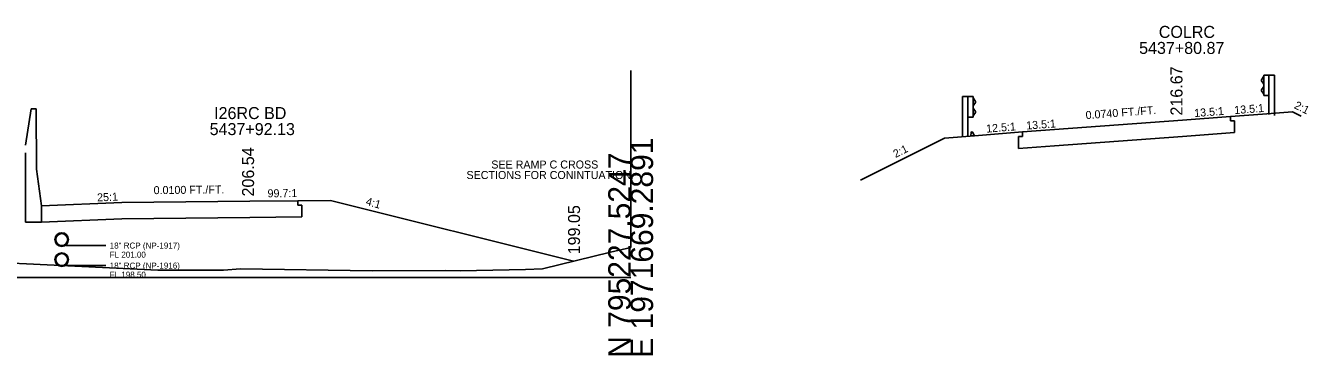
# Model space of a CAD drawing. Extents: x -161 to 1970889, y -4362 to 797231.
# Drawn here: x 1224.4 to 1384.7, y 4490.3 to 4531.4 of the extents above; entities that cross this region are included whole.
import ezdxf

# ---------------------------------------------------------------- set-up
doc = ezdxf.new("R2010")
doc.units = 0
for name, color, linetype in [('RD_GPK_XS_Cell', 7, 'Continuous'), ('RD_XS_Base', 7, 'Continuous'), ('RD_XS_CurbTop', 7, 'Continuous'), ('RD_XS_EarthShd', 7, 'Continuous'), ('RD_XS_ExGround', 7, 'Continuous'), ('RD_XS_GR', 7, 'Continuous'), ('RD_XS_MedBWall', 7, 'Continuous'), ('RD_XS_Pave', 7, 'Continuous'), ('RD_XS_PaveShd', 7, 'Continuous'), ('RD_XS_Pipe', 7, 'Continuous'), ('RD_XS_TieSlope', 7, 'Continuous'), ('RD_XS_TX_Elev_PR', 7, 'Continuous'), ('RD_XS_TX_Misc', 7, 'Continuous'), ('RD_XS_TX_Notes', 7, 'Continuous'), ('RD_XS_TX_Profile', 7, 'Continuous'), ('RD_XS_TX_ShdSlope', 7, 'Continuous'), ('RD_XS_TX_Slope', 7, 'Continuous'), ('RD_XS_TX_Station', 7, 'Continuous')]:
    doc.layers.add(name, color=color, linetype=linetype)

msp = doc.modelspace()

# ---------------------------------------------------------------- linework, layer by layer
at = {"layer": 'RD_GPK_XS_Cell'}
msp.add_line((1150, 4500), (1300, 4500), dxfattribs=at)
at = {"layer": 'RD_XS_Base'}
for p, q in [((1374.97, 4519.56), (1374.97, 4520.12)), ((1375.47, 4519.59), (1374.97, 4519.56)), ((1375.47, 4518.11), (1375.47, 4519.59)), ((1348.97, 4517.63), (1348.97, 4518.19)), ((1368.97, 4517.63), (1375.47, 4518.11)), ((1348.47, 4517.6), (1348.97, 4517.63)), ((1348.47, 4516.12), (1348.47, 4517.6)), ((1352.97, 4516.45), (1348.47, 4516.12)), ((1352.97, 4516.45), (1368.97, 4517.63)), ((1226.38, 4508.42), (1226.38, 4508.98)), ((1258.41, 4509.04), (1258.41, 4509.6)), ((1258.91, 4509.05), (1258.41, 4509.04)), ((1258.91, 4507.57), (1258.91, 4509.05)), ((1236.39, 4507.34), (1226.38, 4506.94)), ((1236.39, 4507.34), (1252.41, 4507.5)), ((1252.41, 4507.5), (1258.91, 4507.57))]:
    msp.add_line(p, q, dxfattribs=at)
at = {"layer": 'RD_XS_CurbTop'}
for p, q in [((1342.5, 4517.68), (1342.56, 4518.11)), ((1342.97, 4517.71), (1342.72, 4518.17)), ((1342.97, 4517.71), (1342.5, 4517.68))]:
    msp.add_line(p, q, dxfattribs=at)
msp.add_ellipse((1342.65, 4518.09), major_axis=(0, 0.131), ratio=0.686, start_param=5.388101, end_param=7.661995, dxfattribs=at)
at = {"layer": 'RD_XS_EarthShd'}
for p, q in [((1374.97, 4520.12), (1378.97, 4520.41)), ((1348.97, 4518.19), (1342.97, 4517.71)), ((1258.41, 4509.6), (1262.48, 4509.64))]:
    msp.add_line(p, q, dxfattribs=at)
at = {"layer": 'RD_XS_ExGround'}
msp.add_lwpolyline([(1222.68, 4501.8), (1224.49, 4501.73), (1240.9, 4500.95), (1249.12, 4500.92), (1251.24, 4501.09), (1267.68, 4500.85), (1276.82, 4500.9), (1278.69, 4500.83), (1286.85, 4501.02), (1289, 4501.12), (1297.5, 4503.18), (1300, 4503.76)], dxfattribs=at)
at = {"layer": 'RD_XS_GR'}
for p, q in [((1379.12, 4525.13), (1378.85, 4524.69)), ((1378.85, 4524.69), (1378.85, 4524.58)), ((1378.85, 4524.58), (1379.12, 4524.14)), ((1379.12, 4525.29), (1379.78, 4525.29)), ((1379.12, 4522.72), (1379.12, 4525.29)), ((1379.78, 4525.29), (1380.45, 4525.29)), ((1379.78, 4525.29), (1379.78, 4520.35)), ((1380.45, 4525.29), (1380.45, 4520.23)), ((1378.85, 4523.43), (1379.12, 4523.87)), ((1378.85, 4523.32), (1378.85, 4523.43)), ((1379.12, 4522.88), (1378.85, 4523.32)), ((1379.12, 4522.72), (1379.78, 4522.72)), ((1342.16, 4522.59), (1341.49, 4522.59)), ((1341.49, 4522.59), (1341.49, 4517.54)), ((1342.82, 4522.59), (1342.16, 4522.59)), ((1342.16, 4522.59), (1342.16, 4517.65)), ((1342.82, 4520.02), (1342.82, 4522.59)), ((1342.82, 4522.43), (1343.1, 4521.99)), ((1343.1, 4521.88), (1342.82, 4521.44)), ((1343.1, 4520.73), (1342.82, 4521.17)), ((1343.1, 4521.99), (1343.1, 4521.88)), ((1342.82, 4520.02), (1342.16, 4520.02)), ((1342.82, 4520.18), (1343.1, 4520.62)), ((1343.1, 4520.62), (1343.1, 4520.73))]:
    msp.add_line(p, q, dxfattribs=at)
at = {"layer": 'RD_XS_MedBWall'}
for p, q in [((1224.38, 4516.52), (1225.05, 4521.06)), ((1225.71, 4521.06), (1225.05, 4521.06)), ((1225.71, 4521.06), (1225.72, 4513.52)), ((1224.38, 4515.56), (1224.38, 4506.94)), ((1226.38, 4508.98), (1225.72, 4513.52)), ((1226.38, 4508.98), (1226.38, 4506.94)), ((1226.38, 4506.94), (1224.38, 4506.94))]:
    msp.add_line(p, q, dxfattribs=at)
at = {"layer": 'RD_XS_Pave'}
for p, q in [((1352.97, 4518.49), (1368.97, 4519.67)), ((1236.39, 4509.38), (1252.41, 4509.54))]:
    msp.add_line(p, q, dxfattribs=at)
at = {"layer": 'RD_XS_PaveShd'}
for p, q in [((1368.97, 4519.67), (1374.97, 4520.12)), ((1352.97, 4518.49), (1348.97, 4518.19)), ((1236.39, 4509.38), (1226.38, 4508.98)), ((1252.41, 4509.54), (1258.41, 4509.6))]:
    msp.add_line(p, q, dxfattribs=at)
at = {"layer": 'RD_XS_Pipe'}
for p, q in [((1229.39, 4504), (1234.39, 4504)), ((1229.39, 4501.5), (1234.39, 4501.5))]:
    msp.add_line(p, q, dxfattribs=at)
for centre, radius in [((1228.89, 4504.75), 0.85), ((1228.89, 4504.75), 0.75), ((1228.89, 4502.25), 0.85), ((1228.89, 4502.25), 0.75)]:
    msp.add_circle(centre, radius, dxfattribs=at)
at = {"layer": 'RD_XS_TieSlope'}
for p, q in [((1378.97, 4520.41), (1382.72, 4520.69)), ((1382.72, 4520.69), (1383.79, 4520.15)), ((1339.22, 4517.41), (1328.71, 4512.16)), ((1342.97, 4517.71), (1339.22, 4517.41)), ((1262.48, 4509.64), (1292.84, 4502.05))]:
    msp.add_line(p, q, dxfattribs=at)
at = {"layer": 'RD_XS_TX_Notes'}
msp.add_line((1300, 4503.76), (1300, 4525.86), dxfattribs=at)

# ---------------------------------------------------------------- texts
at = {"layer": 'RD_GPK_XS_Cell'}
for s, p in [('E 1971669.2891', (1302.8, 4490)), ('N 795227.5247', (1300, 4490))]:
    msp.add_text(s, height=2.8, rotation=90, dxfattribs=at).set_placement(p)
at = {"layer": 'RD_XS_Pipe'}
for s, p in [('18" RCP (NP-1917)', (1234.89, 4503.63)), ('FL 201.00', (1234.89, 4502.5)), ('18" RCP (NP-1916)', (1234.89, 4501.13)), ('FL 198.50', (1234.89, 4500))]:
    msp.add_text(s, height=0.75, dxfattribs=at).set_placement(p)
at = {"layer": 'RD_XS_TX_Elev_PR'}
for s, p in [(' 216.67', (1368.97, 4519.67)), (' 206.54', (1252.93, 4509.57))]:
    msp.add_text(s, height=1.5, rotation=90, dxfattribs=at).set_placement(p)
at = {"layer": 'RD_XS_TX_Misc'}
msp.add_text('199.05', height=1.5, rotation=90, dxfattribs=at).set_placement((1293.67, 4502.91))
at = {"layer": 'RD_XS_TX_Notes'}
for s, p in [('SEE RAMP C CROSS ', (1282.58, 4513.62)), ('SECTIONS FOR CONINTUATION', (1279.48, 4512.31))]:
    msp.add_text(s, height=1, rotation=360, dxfattribs=at).set_placement(p)
at = {"layer": 'RD_XS_TX_Profile'}
msp.add_text('99.7:1', height=1, rotation=0.5747, dxfattribs=at).set_placement((1254.62, 4510.02))
at = {"layer": 'RD_XS_TX_ShdSlope'}
for s, rotation, p in [('13.5:1', 4.2294, (1375.48, 4520.41)), ('12.5:1', 4.5739, (1344.47, 4518.09))]:
    msp.add_text(s, height=1, rotation=rotation, dxfattribs=at).set_placement(p)
at = {"layer": 'RD_XS_TX_Slope'}
for s, rotation, p in [('0.0740 FT./FT.', 4.2294, (1356.9, 4519.78)), ('13.5:1', 4.2294, (1370.47, 4520.04)), ('2:1', 333.435, (1382.85, 4521.19)), ('13.5:1', 4.2294, (1349.47, 4518.48)), ('2:1', 26.565, (1333.11, 4514.92)), ('0.0100 FT./FT.', 0.5747, (1240.38, 4510.42)), ('25:1', 2.2886, (1233.33, 4509.51)), ('4:1', 344.1175, (1266.82, 4509.1))]:
    msp.add_text(s, height=1, rotation=rotation, dxfattribs=at).set_placement(p)
at = {"layer": 'RD_XS_TX_Station'}
for s, p in [('COLRC', (1366.01, 4529.92)), ('5437+80.87', (1363.55, 4527.92)), ('I26RC BD', (1247.94, 4519.79)), ('5437+92.13', (1247.38, 4517.79))]:
    msp.add_text(s, height=1.5, dxfattribs=at).set_placement(p)

doc.saveas('drawing.dxf')
